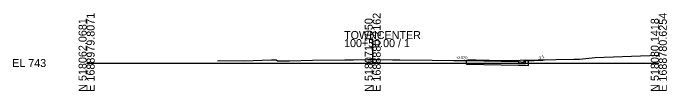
# Model space of a CAD drawing. Extents: x -26 to 203, y -10 to 4027.
# Drawn here: x -25.7 to 202.8, y 990.3 to 1017.4 of the extents above; entities that cross this region are included whole.
import ezdxf

# ---------------------------------------------------------------- set-up
doc = ezdxf.new("R2010")
doc.units = 0
for name, color, linetype in [('Default', 7, 'Continuous'), ('DESIGN - SHEET - Light Grid', 7, 'Continuous'), ('DESIGN - TYPICAL - Finished Grade and Subgrade', 7, 'Continuous'), ('DESIGN - TYPICAL - Finished Grade Slopes Text', 7, 'Continuous'), ('SURVEY - GROUND - Top of Ground', 7, 'Continuous')]:
    doc.layers.add(name, color=color, linetype=linetype)

msp = doc.modelspace()

# ---------------------------------------------------------------- linework, layer by layer
at = {"layer": 'DESIGN - SHEET - Light Grid'}
for p, q in [((100, 1000), (100, 1008.34)), ((0, 1000), (100, 1000)), ((100, 1000), (200, 1000))]:
    msp.add_line(p, q, dxfattribs=at)
at = {"layer": 'DESIGN - TYPICAL - Finished Grade and Subgrade'}
for p, q in [((159.44, 1000.94), (160.07, 1001.15)), ((132.78, 1000.85), (150.94, 1000.49)), ((132.78, 999.6), (132.78, 1000.85)), ((132.78, 999.6), (150.94, 999.24)), ((150.94, 1000.49), (152.94, 1000.32)), ((150.94, 1000.49), (150.94, 999.87)), ((150.94, 999.87), (153.44, 999.82)), ((150.94, 999.24), (154.44, 999.17)), ((152.94, 1000.32), (152.95, 1000.8)), ((152.95, 1000.8), (153.44, 1000.82)), ((153.44, 1000.82), (159.44, 1000.94)), ((153.44, 999.82), (153.44, 1000.82)), ((154.44, 999.17), (154.44, 1000.84))]:
    msp.add_line(p, q, dxfattribs=at)
at = {"layer": 'SURVEY - GROUND - Top of Ground'}
msp.add_lwpolyline([(45.72, 1000.71), (46.5, 1000.87), (55.01, 1000.71), (64.61, 1001.09), (66.23, 1001.09), (66.77, 1000.75), (70.96, 1000.82), (78.93, 1000.99), (90.29, 1001.08), (90.83, 1001.1), (93.25, 1001.15), (98.32, 1001.28), (100, 1001.27), (102.45, 1001.27), (106.98, 1001.17), (109.46, 1001.14), (120.74, 1001.03), (128.41, 1000.93), (132.78, 1000.85), (133.34, 1001.16), (136.22, 1001.12), (145.27, 1000.92), (170.29, 1001.31), (172.31, 1001.4), (177.71, 1001.91), (200, 1002.78)], dxfattribs=at)

# ---------------------------------------------------------------- texts
at = {"layer": 'Default'}
msp.add_text('744.27', height=1, dxfattribs=at).set_placement((97.99, 1000.13))
at = {"layer": 'DESIGN - SHEET - Light Grid'}
for s, p in [('E 1688979.8071', (2.8, 990)), ('E 1688880.2162', (102.8, 990)), ('E 1688780.6254', (202.8, 990)), ('N 518062.0681', (0, 990)), ('N 518071.1050', (100, 990)), ('N 518080.1418', (200, 990))]:
    msp.add_text(s, height=2.8, rotation=90, dxfattribs=at).set_placement(p)
for s, p in [('TOWNCENTER', (90, 1008.34)), ('100+50.00 / 1', (90, 1005.54)), ('EL 743', (-26, 998.6))]:
    msp.add_text(s, height=2.8, dxfattribs=at).set_placement(p)
at = {"layer": 'DESIGN - TYPICAL - Finished Grade Slopes Text'}
for s, rotation, p in [('-0.020', 358.8542, (129.17, 1001.4)), ('3:1', 18.4349, (158.23, 1001.23))]:
    msp.add_text(s, height=1, rotation=rotation, dxfattribs=at).set_placement(p)

doc.saveas('drawing.dxf')
